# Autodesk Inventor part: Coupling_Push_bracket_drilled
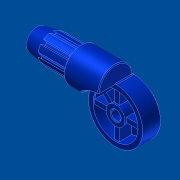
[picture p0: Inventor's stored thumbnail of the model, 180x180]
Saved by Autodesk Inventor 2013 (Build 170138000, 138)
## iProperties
Shininess: 69.0
Length Units: 11269
Angle Units: 11279
Time Units: 11290
Mass Units: 11283
Length Display Precision: 3
Angle Display Precision: 2
Created: 2001-04
Part Number: Coupling_Push_bracket_drilled
Material: Standard
Document SubType Name: Modellieren
Designer: dl
Density: 1 g/cm^3
Density: 0.0
Volumn: 0.0
Area: 0.0
PropertySet Name: Model Information
Control State: 0
Master: False
Checked Out: False
Author: dl
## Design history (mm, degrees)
derived "Gelenkstück Schubbügel.ipt"
sketch "Sketch1"
  geometry: L1 (-28.75, 0)-(6.25, 0) reference; L2 (11.25, 10.5)-(11.25, -10.5) reference; C1 r 2.5 at (21.25, 0); 2 further points
  constraints: 1 centre point
  dimensions: "d4" = 5 diameter of C1; "d5" = 0 distance from line of L1 C1.centre; "d6" = 10 distance from line of L2 C1.centre
extrude "Extrusion1" cut sketch "Sketch1" stored distance "d7" = 10; taper "d8" = 0 deg
body "Solid1"
workaxis "Work Axis1"
workplane "Work Plane1"
tag "TaggingFeature2"
feature "DerivedBody::Gelenkstück Schubbügel.ipt" dims "d1" = 10
other parameters: "d2" = 0, "d3" = 0
